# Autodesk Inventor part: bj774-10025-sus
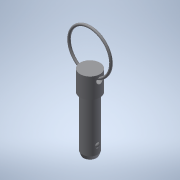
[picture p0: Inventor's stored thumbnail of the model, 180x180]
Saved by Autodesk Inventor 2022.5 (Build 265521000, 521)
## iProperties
Created: 2016-12
Part Number: bj774-10025-sus
Material: 一般
Document SubType Name: Modeling
Designer: imaocorp
Density: 1 g/cm^3
Appearance: 既定
Author: imaocorp
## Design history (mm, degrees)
node "bj774-10025-sus.x_t1"
node "bj774-10025-sus"
node "Base1"
